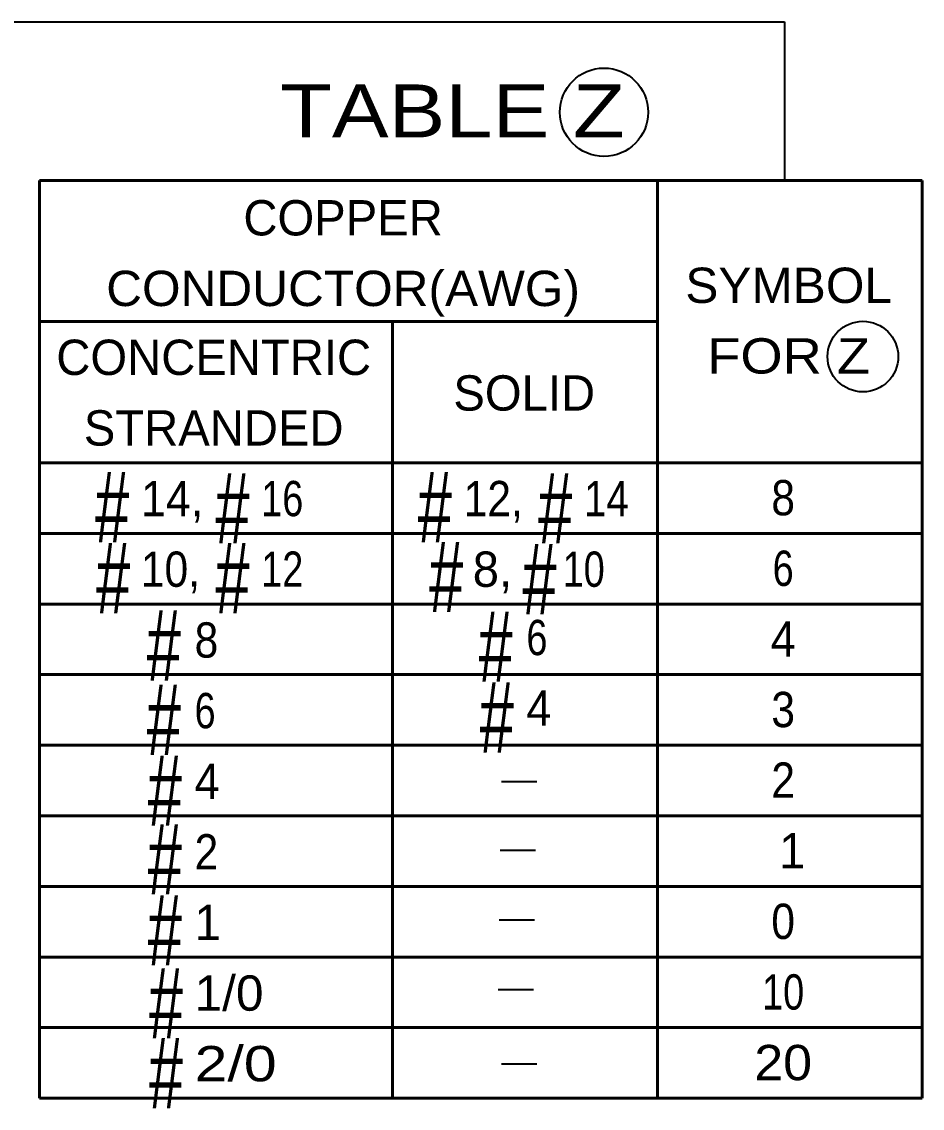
# Model space of a CAD drawing. Extents: x -1 to 679, y 0 to 440.
# Drawn here: x 179.8 to 230.8, y 74.2 to 135.8 of the extents above; entities that cross this region are included whole.
import ezdxf
from ezdxf.enums import TextEntityAlignment as Align

# ---------------------------------------------------------------- set-up
doc = ezdxf.new("R2010")
doc.units = 0
doc.header["$LTSCALE"] = 0.8
doc.layers.add('1', color=7, linetype='Continuous', lineweight=53)

msp = doc.modelspace()

# ---------------------------------------------------------------- linework, layer by layer
at = {"layer": '1', "lineweight": 35}
for p, q in [((140.1378, 135.7618), (223.051, 135.7618)), ((223.051, 135.7618), (223.051, 126.7763)), ((207.0118, 92.729), (209.0118, 92.729)), ((206.9488, 88.839), (208.9488, 88.839)), ((206.8871, 84.8843), (208.8871, 84.8843)), ((206.8253, 80.9297), (208.8253, 80.9297)), ((207.0107, 76.728), (209.0107, 76.728))]:
    msp.add_line(p, q, dxfattribs=at)
at = {"layer": '1'}
for p, q in [((180.8449, 126.7763), (180.8449, 74.7763)), ((180.8449, 126.7763), (230.8449, 126.7763)), ((215.8449, 126.7763), (215.8449, 74.7763)), ((230.8449, 126.7763), (230.8449, 74.7763)), ((180.8449, 118.7763), (215.8449, 118.7763)), ((200.8449, 118.7763), (200.8449, 74.7763)), ((180.8449, 110.7763), (230.8449, 110.7763)), ((180.8449, 106.7763), (230.8449, 106.7763)), ((180.8449, 102.7763), (230.8449, 102.7763)), ((180.8449, 98.7763), (230.8449, 98.7763)), ((180.8449, 94.7763), (230.8449, 94.7763)), ((180.8449, 90.7763), (230.8449, 90.7763)), ((180.8449, 86.7763), (230.8449, 86.7763)), ((180.8449, 82.7763), (230.8449, 82.7763)), ((180.8449, 78.7763), (230.8449, 78.7763)), ((180.8449, 74.7763), (230.8449, 74.7763))]:
    msp.add_line(p, q, dxfattribs=at)
at = {"layer": '1', "lineweight": 40}
msp.add_circle((212.8201, 130.6363), 2.5, dxfattribs=at)
at = {"layer": '1', "lineweight": 35}
msp.add_circle((227.4827, 116.7914), 2, dxfattribs=at)

# ---------------------------------------------------------------- texts
at = {"layer": '1'}
for s, height, width, p in [('TABLE Z', 3, 1.2, (194.4697, 129.2106)), ('#', 4, 0.65, (183.9963, 106.2695)), ('#', 4, 0.65, (190.8122, 106.2057)), ('#', 4, 0.65, (202.2782, 106.2695)), ('#', 4, 0.65, (209.0942, 106.2057)), ('14,', 2, 0.95, (186.5941, 107.7492)), ('16', 2, 0.8, (193.41, 107.7492)), ('12,', 2, 0.9, (204.8761, 107.7492)), ('14', 2, 0.85, (211.692, 107.7492)), ('#', 4, 0.65, (184.06, 102.2551)), ('#', 4, 0.65, (190.8122, 102.255)), ('#', 4, 0.65, (202.9152, 102.3188)), ('#', 4, 0.65, (208.2023, 102.1913)), ('10,', 2, 0.9, (186.5941, 103.7493)), ('12', 2, 0.8, (193.41, 103.7493)), ('10', 2, 0.8, (210.4817, 103.7492)), ('#', 4, 0.65, (186.9264, 98.4317)), ('#', 4, 0.65, (205.718, 98.3718)), ('8', 2, 0.9, (189.6344, 99.7376)), ('6', 2, 0.8, (208.426, 99.8794)), ('#', 4, 0.65, (186.9264, 94.23)), ('#', 4, 0.65, (205.7798, 94.3554)), ('4', 2, 0.95, (208.426, 95.8794)), ('6', 2, 0.8, (189.6344, 95.7376)), ('#', 4, 0.65, (186.9882, 90.2136)), ('4', 2, 0.95, (189.6344, 91.7376)), ('#', 4, 0.65, (186.9882, 86.3208)), ('2', 2, 0.9, (189.6344, 87.7376)), ('#', 4, 0.65, (186.9882, 82.3044)), ('#', 4, 0.65, (187.0499, 78.1644)), ('1/0', 2, 1.05, (189.6344, 79.7376)), ('#', 4, 0.65, (187.0499, 74.2098)), ('2/0', 2, 1.25, (189.6344, 75.7376))]:
    msp.add_text(s, height=height, dxfattribs=dict(at, width=width)).set_placement(p)
for s, p in [('COPPER', (198.0441, 123.6556)), ('CONCENTRIC', (190.7163, 115.7517)), ('STRANDED', (190.7162, 111.7517)), ('1', (223.4809, 87.7995))]:
    msp.add_text(s, height=2, dxfattribs=at).set_placement(p, align=Align.CENTER)
for s, width, p in [('CONDUCTOR(AWG)', 1.05, (198.0441, 119.6556)), ('SYMBOL', 1.05, (223.2772, 119.8311)), ('FOR Z', 1.15, (223.2771, 115.8311)), ('8', 0.9, (222.967, 107.7995)), ('6', 0.8, (222.967, 103.7995)), ('4', 0.95, (222.9669, 99.7995)), ('3', 0.9, (222.967, 95.7995)), ('2', 0.9, (222.967, 91.7995)), ('0', 0.9, (222.967, 83.7995)), ('10', 0.8, (222.967, 79.7995)), ('20', 1.1, (222.9669, 75.7995))]:
    msp.add_text(s, height=2, dxfattribs=dict(at, width=width)).set_placement(p, align=Align.CENTER)
for s, p in [('SOLID', (204.2887, 113.7318)), ('8,', (205.3858, 103.7493)), ('1', (189.6344, 83.7376))]:
    msp.add_text(s, height=2, dxfattribs=at).set_placement(p)

doc.saveas('drawing.dxf')
